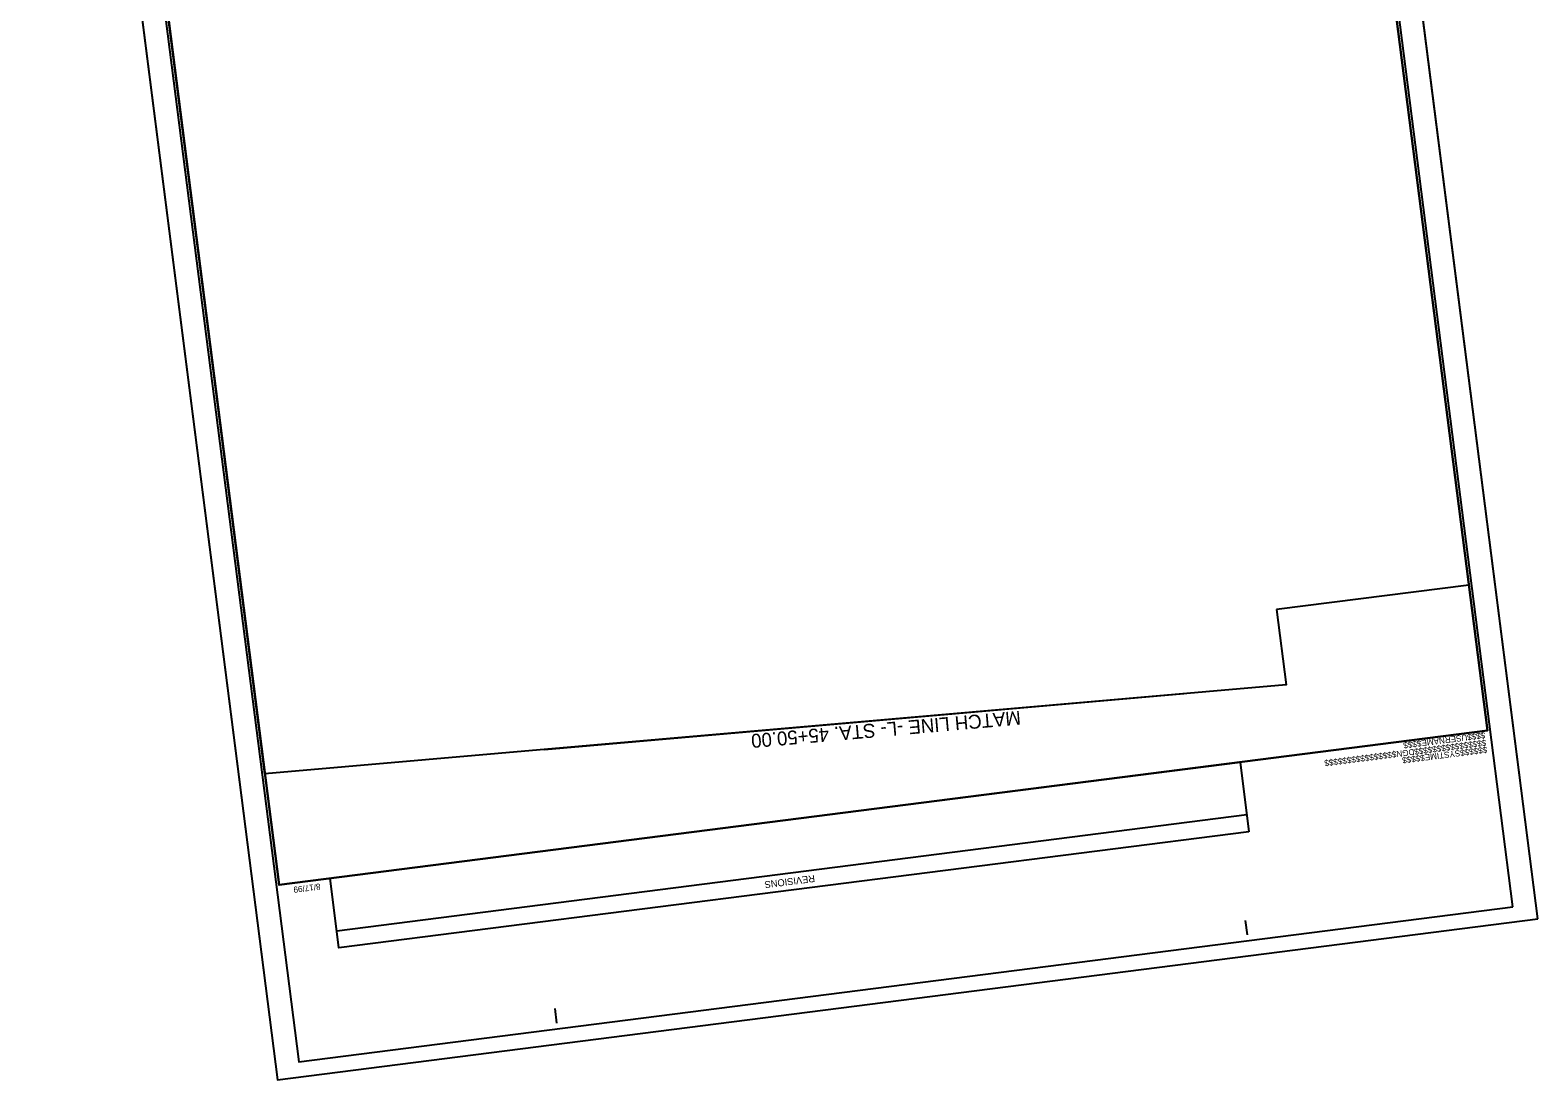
# Model space of a CAD drawing. Extents: x 2368054 to 2369353, y 804567 to 806376.
# Drawn here: x 2368054 to 2369353, y 804567 to 805472 of the extents above; entities that cross this region are included whole.
import ezdxf

# ---------------------------------------------------------------- set-up
doc = ezdxf.new("R2010")
doc.units = 0
for name, color, linetype in [('Old_Level_10', 7, 'Continuous'), ('Old_Level_15', 7, 'Continuous'), ('Old_Level_2', 7, 'Continuous'), ('Old_Level_4', 7, 'Continuous'), ('Old_Level_6', 7, 'Continuous'), ('Old_Level_61', 7, 'Continuous'), ('Old_Level_62', 7, 'Continuous'), ('Old_Level_63', 7, 'Continuous'), ('Plot Shape CELL', 7, 'Continuous'), ('User Information Notes CELL', 7, 'Continuous')]:
    doc.layers.add(name, color=color, linetype=linetype)

msp = doc.modelspace()

# ---------------------------------------------------------------- linework, layer by layer
at = {"layer": 'Old_Level_10'}
msp.add_lwpolyline([(2368268.4, 804735.2), (2369309.9, 804868.2), (2369119.8, 806356.1), (2368288.1, 806249.9), (2368318.4, 806012.6), (2368108.6, 805985.8)], close=True, dxfattribs=at)
at = {"layer": 'Old_Level_15'}
for p, q in [((2369353.3, 804705.9), (2369140, 806375.8)), ((2368053.8, 806237.1), (2368267.1, 804567.2)), ((2368267.1, 804567.2), (2369353.3, 804705.9))]:
    msp.add_line(p, q, dxfattribs=at)
at = {"layer": 'Old_Level_2'}
msp.add_lwpolyline([(2369128.1, 804972.4), (2369136.3, 804907.6), (2368256.1, 804830.9), (2368108.6, 805985.8), (2368318.4, 806012.6), (2368297.7, 806174.5), (2369009.7, 806268.6), (2369034.7, 806345.2), (2369119.8, 806356.1), (2369293.9, 804993.3)], close=True, dxfattribs=at)
msp.add_lwpolyline([(2369128.1, 804972.4), (2369136.3, 804907.6), (2368256.1, 804830.9), (2368108.6, 805985.8), (2368318.4, 806012.6), (2368297.7, 806174.5), (2369009.7, 806268.6), (2369034.7, 806345.2), (2369119.8, 806356.1), (2369293.9, 804993.3)], close=True, dxfattribs=at)
at = {"layer": 'Old_Level_4'}
msp.add_lwpolyline([(2369331.8, 804716.3), (2369120.7, 806368.8), (2368074.2, 806235.2), (2368285.3, 804582.6)], close=True, dxfattribs=at)
at = {"layer": 'Old_Level_6'}
msp.add_lwpolyline([(2369353.3, 804705.9), (2369140, 806375.8), (2368053.8, 806237.1), (2368267.1, 804567.2)], close=True, dxfattribs=at)
at = {"layer": 'Old_Level_62'}
msp.add_line((2368497.2, 804851.9), (2369048.2, 804899.9), dxfattribs=at)
at = {"layer": 'Old_Level_63'}
msp.add_line((2368761.4, 804874.9), (2368761.4, 804874.9), dxfattribs=at)
at = {"layer": 'Plot Shape CELL'}
for p, q in [((2369309.9, 804868.2), (2369309.9, 804868.2)), ((2368268.3, 804735.2), (2368268.3, 804735.2)), ((2369103, 804692.1), (2369101.4, 804704.5)), ((2368507.9, 804616.1), (2368506.3, 804628.5))]:
    msp.add_line(p, q, dxfattribs=at)
for points in [[(2368078.3, 806223.1), (2368268.3, 804735.2), (2369309.9, 804868.2), (2369119.8, 806356.1)], [(2369309.9, 804868.2), (2368268.4, 804735.2), (2368103.6, 806024.7), (2368252.5, 806043.7), (2368227.1, 806242.1), (2369119.8, 806356.1)]]:
    msp.add_lwpolyline(points, close=True, dxfattribs=at)
at = {"layer": 'User Information Notes CELL'}
msp.add_line((2369102.4, 804795.4), (2368318.2, 804695.2), dxfattribs=at)
msp.add_lwpolyline([(2369104.3, 804780.9), (2368320, 804680.8), (2368312.3, 804740.8), (2369096.6, 804841)], close=True, dxfattribs=at)

# ---------------------------------------------------------------- texts
at = {"layer": 'Old_Level_61'}
msp.add_text('MATCH LINE -L- STA. 45+50.00', height=12, rotation=184.9764, dxfattribs=at).set_placement((2368907.1, 804885.2))
at = {"layer": 'Plot Shape CELL'}
for s, p in [('$$$$$$$$$$$$$$$$DGN$$$$$$$$$$$$$$$$', (2369308.5, 804860.3)), ('$$$$USERNAME$$$$', (2369307.6, 804866.8)), ('$$$$$$SYSTIME$$$$$', (2369309.3, 804854.3)), ('8/17/99', (2368303.7, 804736.4))]:
    msp.add_text(s, height=5.25, rotation=187.2784, dxfattribs=at).set_placement(p)
at = {"layer": 'User Information Notes CELL'}
msp.add_text('REVISIONS', height=6, rotation=187.2784, dxfattribs=at).set_placement((2368729.8, 804743.7))

doc.saveas('drawing.dxf')
